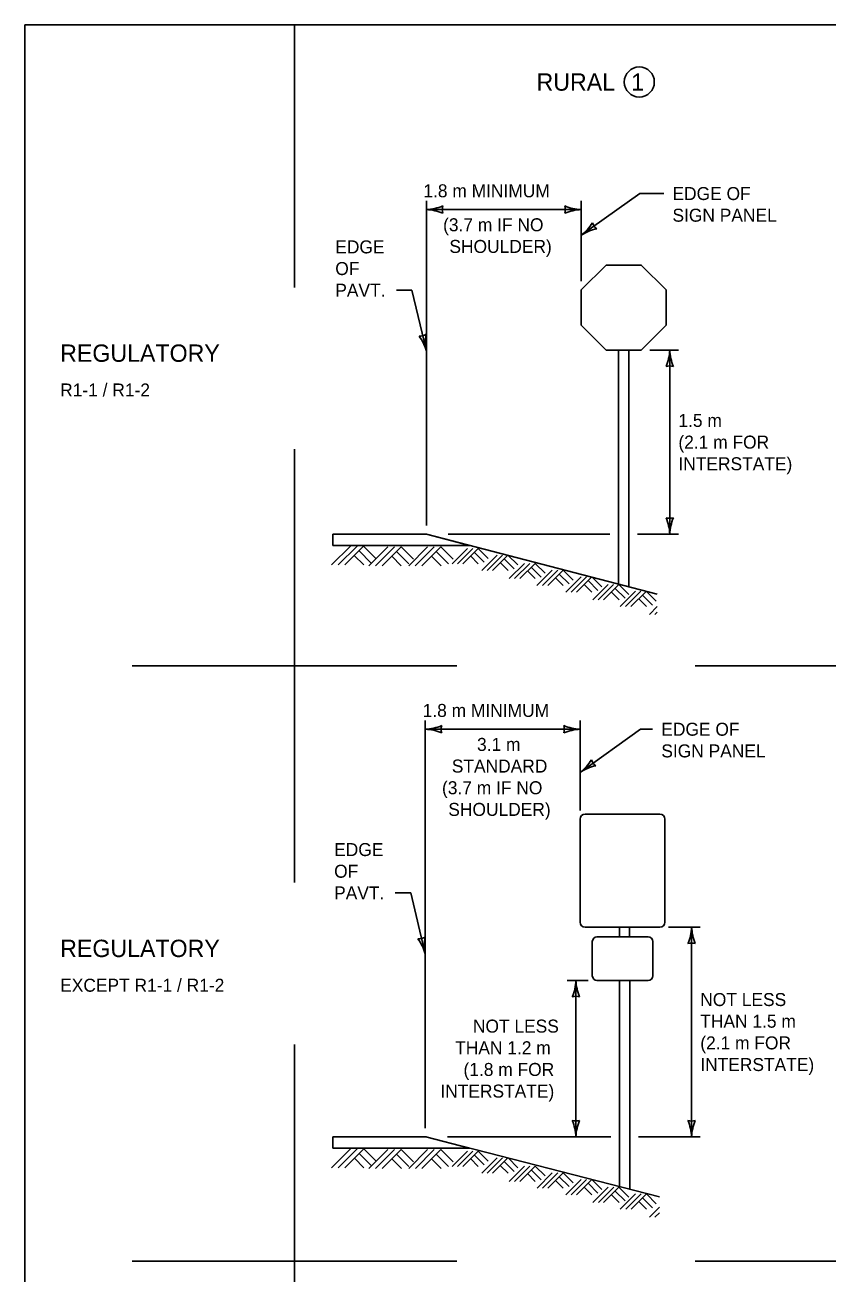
# Model space of a CAD drawing. Extents: x 49991.4 to 50021, y 49987.6 to 50011.4.
# Drawn here: x 49999.38 to 50003.09, y 49993.24 to 49999 of the extents above; entities that cross this region are included whole.
import ezdxf

# ---------------------------------------------------------------- set-up
doc = ezdxf.new("R2010")
doc.units = 0
for name, color, linetype in [('Level 1', 7, 'Continuous'), ('Level 2', 7, 'Continuous'), ('Level 3', 7, 'Continuous')]:
    doc.layers.add(name, color=color, linetype=linetype)

msp = doc.modelspace()

# ---------------------------------------------------------------- linework, layer by layer
at = {"layer": 'Level 1'}
for p, q in [((50002.124, 49996.4185), (50002.124, 49997.4987)), ((50002.1727, 49996.4059), (50002.1727, 49997.4987)), ((50001.2375, 49996.649), (50000.8056, 49996.649)), ((50000.8056, 49996.649), (50000.8056, 49996.5973)), ((50001.2374, 49996.649), (50000.8056, 49996.649)), ((50000.8056, 49996.649), (50000.8056, 49996.5973)), ((50001.2374, 49996.649), (50002.3037, 49996.3718)), ((50001.4363, 49996.5973), (50001.2374, 49996.649)), ((50000.7994, 49996.5068), (50000.8867, 49996.5941)), ((50000.8056, 49996.5973), (50001.4363, 49996.5973)), ((50000.8056, 49996.5973), (50001.4363, 49996.5973)), ((50000.83, 49996.5068), (50000.9173, 49996.5941)), ((50000.8605, 49996.5068), (50000.9477, 49996.5941)), ((50000.9263, 49996.5725), (50000.983, 49996.5158)), ((50000.9477, 49996.5941), (50001.0046, 49996.5373)), ((50000.9721, 49996.5031), (50001.0594, 49996.5905)), ((50001.0027, 49996.5031), (50001.0901, 49996.5905)), ((50001.0332, 49996.5031), (50001.1206, 49996.5905)), ((50001.099, 49996.5688), (50001.1558, 49996.5122)), ((50001.1206, 49996.5905), (50001.1774, 49996.5336)), ((50001.1556, 49996.5031), (50001.2429, 49996.5905)), ((50001.1863, 49996.5031), (50001.2736, 49996.5905)), ((50001.2167, 49996.5031), (50001.3041, 49996.5905)), ((50001.2825, 49996.5688), (50001.3393, 49996.5122)), ((50001.3041, 49996.5905), (50001.361, 49996.5336)), ((50001.3558, 49996.5125), (50001.4265, 49996.5833)), ((50001.3807, 49996.5125), (50001.4514, 49996.5833)), ((50001.4053, 49996.5125), (50001.4761, 49996.5833)), ((50001.4348, 49996.5977), (50001.4348, 49996.5973)), ((50001.4361, 49996.5973), (50001.4361, 49996.5973)), ((50001.4361, 49996.5973), (50001.4361, 49996.5973)), ((50001.4361, 49996.5973), (50001.4361, 49996.5973)), ((50001.4585, 49996.5659), (50001.5046, 49996.52)), ((50001.4761, 49996.5833), (50001.5222, 49996.5373)), ((50000.9046, 49996.5508), (50000.9488, 49996.5068)), ((50001.0774, 49996.5471), (50001.1215, 49996.5031)), ((50001.2608, 49996.5471), (50001.305, 49996.5031)), ((50001.4411, 49996.5483), (50001.4769, 49996.5125)), ((50001.4933, 49996.4819), (50001.564, 49996.5527)), ((50001.5181, 49996.4819), (50001.5889, 49996.5527)), ((50001.5428, 49996.4819), (50001.6135, 49996.5527)), ((50001.5785, 49996.5176), (50001.6145, 49996.4819)), ((50001.5961, 49996.5352), (50001.642, 49996.4892)), ((50001.6135, 49996.5527), (50001.6595, 49996.5067)), ((50001.6191, 49996.4437), (50001.6898, 49996.5143)), ((50001.6439, 49996.4437), (50001.7145, 49996.5143)), ((50001.6684, 49996.4437), (50001.7392, 49996.5143)), ((50001.7392, 49996.5143), (50001.7853, 49996.4683)), ((50001.7043, 49996.4794), (50001.7401, 49996.4437)), ((50001.7218, 49996.497), (50001.7678, 49996.451)), ((50001.748, 49996.4117), (50001.8187, 49996.4826)), ((50001.773, 49996.4117), (50001.8438, 49996.4826)), ((50001.7977, 49996.4117), (50001.8684, 49996.4826)), ((50001.8334, 49996.4474), (50001.8692, 49996.4117)), ((50001.8509, 49996.4651), (50001.8969, 49996.4192)), ((50001.8684, 49996.4826), (50001.9145, 49996.4365)), ((50001.8808, 49996.3813), (50001.9515, 49996.4521)), ((50001.9057, 49996.3813), (50001.9765, 49996.4521)), ((50001.9304, 49996.3813), (50001.9999, 49996.4508)), ((50002.0035, 49996.4499), (50002.0473, 49996.4063)), ((50001.9662, 49996.417), (50002.0018, 49996.3813)), ((50001.9837, 49996.4345), (50002.0296, 49996.3889)), ((50002.0063, 49996.3456), (50002.077, 49996.4164)), ((50002.0314, 49996.3456), (50002.1021, 49996.4164)), ((50002.0559, 49996.3456), (50002.1266, 49996.4164)), ((50002.1091, 49996.3989), (50002.1552, 49996.3529)), ((50002.1266, 49996.4164), (50002.1728, 49996.3703)), ((50002.1327, 49996.3145), (50002.2033, 49996.3853)), ((50002.1575, 49996.3145), (50002.2283, 49996.3853)), ((50002.1821, 49996.3145), (50002.2527, 49996.3851)), ((50002.2533, 49996.3849), (50002.299, 49996.3393)), ((50002.0916, 49996.3813), (50002.1274, 49996.3456)), ((50002.2179, 49996.3502), (50002.2537, 49996.3145)), ((50002.2354, 49996.3677), (50002.2814, 49996.3219)), ((50002.268, 49996.2787), (50002.3037, 49996.3144)), ((50002.2929, 49996.2787), (50002.3037, 49996.2895)), ((50001.97, 49995.3563), (50002.3161, 49995.3563)), ((50001.9475, 49994.8576), (50001.9475, 49995.3338)), ((50002.3386, 49995.3338), (50002.3386, 49994.8576)), ((50002.3161, 49994.8351), (50001.97, 49994.8351)), ((50002.1286, 49994.7902), (50002.1286, 49994.8351)), ((50002.1748, 49994.7902), (50002.1748, 49994.8351)), ((50002.0251, 49994.7902), (50002.2611, 49994.7902)), ((50002.0036, 49994.611), (50002.0036, 49994.7687)), ((50002.2826, 49994.7687), (50002.2826, 49994.611)), ((50002.2611, 49994.5895), (50002.0251, 49994.5895)), ((50002.1286, 49993.6382), (50002.1286, 49994.5895)), ((50002.1286, 49993.6382), (50002.1286, 49994.5895)), ((50002.1772, 49993.6257), (50002.1772, 49994.5895)), ((50002.1772, 49993.6257), (50002.1772, 49994.5895)), ((50001.2376, 49993.8673), (50000.8056, 49993.8673)), ((50000.8056, 49993.8673), (50000.8056, 49993.8156)), ((50001.2343, 49993.8673), (50000.8056, 49993.8673)), ((50000.8056, 49993.8673), (50000.8056, 49993.8156)), ((50001.2343, 49993.8673), (50002.3135, 49993.5908)), ((50001.4361, 49993.8156), (50001.2343, 49993.8673)), ((50000.7995, 49993.725), (50000.8868, 49993.8124)), ((50000.8056, 49993.8156), (50001.4362, 49993.8156)), ((50000.8056, 49993.8156), (50001.4361, 49993.8156)), ((50000.8301, 49993.725), (50000.9175, 49993.8124)), ((50000.8606, 49993.725), (50000.9479, 49993.8124)), ((50000.9479, 49993.8124), (50001.0048, 49993.7556)), ((50000.9723, 49993.7214), (50001.0596, 49993.8087)), ((50001.003, 49993.7214), (50001.0903, 49993.8087)), ((50001.0334, 49993.7214), (50001.1207, 49993.8087)), ((50001.1207, 49993.8087), (50001.1776, 49993.752)), ((50001.1558, 49993.7214), (50001.2431, 49993.8087)), ((50001.1865, 49993.7214), (50001.2738, 49993.8087)), ((50001.2169, 49993.7214), (50001.3042, 49993.8087)), ((50001.3042, 49993.8087), (50001.3611, 49993.752)), ((50001.356, 49993.7309), (50001.4267, 49993.8016)), ((50001.3809, 49993.7309), (50001.4516, 49993.8016)), ((50001.4055, 49993.7309), (50001.4762, 49993.8016)), ((50001.4362, 49993.8156), (50001.4362, 49993.8156)), ((50001.4762, 49993.8016), (50001.5223, 49993.7556)), ((50000.9047, 49993.7691), (50000.9489, 49993.725)), ((50000.9264, 49993.7908), (50000.9832, 49993.7341)), ((50001.0776, 49993.7654), (50001.1217, 49993.7214)), ((50001.0991, 49993.7871), (50001.1559, 49993.7305)), ((50001.2611, 49993.7654), (50001.3052, 49993.7214)), ((50001.2826, 49993.7871), (50001.3394, 49993.7305)), ((50001.4413, 49993.7666), (50001.4772, 49993.7309)), ((50001.4587, 49993.7842), (50001.5048, 49993.7383)), ((50001.4934, 49993.7002), (50001.5641, 49993.7709)), ((50001.5183, 49993.7002), (50001.589, 49993.7709)), ((50001.5429, 49993.7002), (50001.6131, 49993.7703)), ((50001.5787, 49993.7358), (50001.6146, 49993.7002)), ((50001.5963, 49993.7535), (50001.6422, 49993.7076)), ((50001.6148, 49993.7698), (50001.6597, 49993.7249)), ((50001.6192, 49993.6619), (50001.6899, 49993.7326)), ((50001.6441, 49993.6619), (50001.7148, 49993.7326)), ((50001.6687, 49993.6619), (50001.7394, 49993.7326)), ((50001.7045, 49993.6976), (50001.7402, 49993.6619)), ((50001.722, 49993.7152), (50001.768, 49993.6693)), ((50001.7394, 49993.7326), (50001.7855, 49993.6866)), ((50001.7482, 49993.6301), (50001.8189, 49993.7009)), ((50001.7732, 49993.6301), (50001.8439, 49993.7009)), ((50001.7978, 49993.6301), (50001.8685, 49993.7009)), ((50001.8511, 49993.6834), (50001.897, 49993.6375)), ((50001.8685, 49993.7009), (50001.9146, 49993.6548)), ((50001.8336, 49993.6657), (50001.8694, 49993.6301)), ((50001.881, 49993.5996), (50001.9517, 49993.6703)), ((50001.9059, 49993.5996), (50001.9767, 49993.6703)), ((50001.9306, 49993.5996), (50002.0013, 49993.6703)), ((50001.9664, 49993.6353), (50002.0021, 49993.5996)), ((50001.9839, 49993.6529), (50002.0298, 49993.6072)), ((50002.0013, 49993.6703), (50002.0474, 49993.6245)), ((50002.0066, 49993.5639), (50002.0773, 49993.6347)), ((50002.0315, 49993.5639), (50002.1023, 49993.6347)), ((50002.056, 49993.5639), (50002.1268, 49993.6347)), ((50002.1268, 49993.6347), (50002.173, 49993.5886)), ((50002.0918, 49993.5996), (50002.1276, 49993.5639)), ((50002.1093, 49993.6172), (50002.1554, 49993.5713)), ((50002.1328, 49993.5328), (50002.2035, 49993.6035)), ((50002.1577, 49993.5328), (50002.2285, 49993.6035)), ((50002.1823, 49993.5328), (50002.2531, 49993.6035)), ((50002.2182, 49993.5685), (50002.2539, 49993.5328)), ((50002.2357, 49993.5861), (50002.2816, 49993.5402)), ((50002.2531, 49993.6035), (50002.2992, 49993.5576)), ((50002.2682, 49993.4969), (50002.3135, 49993.5422)), ((50002.2931, 49993.4969), (50002.3135, 49993.5173))]:
    msp.add_line(p, q, dxfattribs=at)
for points in [[(49999.3835, 49998.9992), (50016.7501, 49998.9992), (50016.7501, 49987.7988), (49999.3835, 49987.7988)], [(50002.0669, 49997.8908), (50002.2297, 49997.8908), (50002.3444, 49997.7761), (50002.3444, 49997.6134), (50002.2297, 49997.4987), (50002.0669, 49997.4987), (50001.9523, 49997.6134), (50001.9523, 49997.7761)]]:
    msp.add_lwpolyline(points, close=True, dxfattribs=at)
for centre, radius, start, end in [((50001.97, 49995.3338), 0.0225, 90, 180), ((50002.3161, 49995.3338), 0.0225, 0, 90), ((50001.97, 49994.8576), 0.0225, 180, 270), ((50002.3161, 49994.8576), 0.0225, 270, 0), ((50002.0251, 49994.7687), 0.0215, 90, 180), ((50002.2611, 49994.7687), 0.0215, 0, 90), ((50002.0251, 49994.611), 0.0215, 180, 270), ((50002.2611, 49994.611), 0.0215, 270, 0)]:
    msp.add_arc(centre, radius, start, end, dxfattribs=at)
at = {"layer": 'Level 2'}
msp.add_circle((50002.2206, 49998.7359), 0.0693, dxfattribs=at)
at = {"layer": 'Level 3'}
for p, q in [((50000.6286, 49998.9992), (50000.6286, 49997.788)), ((50001.2375, 49996.689), (50001.2375, 49998.187)), ((50001.9523, 49998.0283), (50002.223, 49998.2211)), ((50001.9523, 49997.8161), (50001.9523, 49998.187)), ((50002.223, 49998.2211), (50002.3338, 49998.2211)), ((50001.2375, 49998.147), (50001.9523, 49998.147)), ((50001.0987, 49997.7749), (50001.1707, 49997.7749)), ((50001.1707, 49997.7749), (50001.2375, 49997.4934)), ((50002.2697, 49997.4987), (50002.4012, 49997.4987)), ((50002.3612, 49997.4987), (50002.3612, 49996.649)), ((50000.6286, 49995.0407), (50000.6286, 49997.0407)), ((50001.3374, 49996.649), (50002.084, 49996.649)), ((50002.2127, 49996.649), (50002.4012, 49996.649)), ((49999.8786, 49996.0407), (50001.3786, 49996.0407)), ((50002.4787, 49996.0407), (50003.9787, 49996.0407)), ((50001.2323, 49993.9073), (50001.2323, 49995.7886)), ((50001.9475, 49995.3738), (50001.9475, 49995.7886)), ((50001.9475, 49995.7486), (50001.2323, 49995.7486)), ((50001.9475, 49995.5496), (50002.2269, 49995.7486)), ((50002.2269, 49995.7486), (50002.2823, 49995.7486)), ((50001.0935, 49994.9932), (50001.1655, 49994.9932)), ((50001.1655, 49994.9932), (50001.2323, 49994.7117)), ((50002.3561, 49994.8351), (50002.5022, 49994.8351)), ((50002.4622, 49993.8669), (50002.4622, 49994.8351)), ((50001.888, 49994.5895), (50001.9851, 49994.5895)), ((50001.928, 49993.8673), (50001.928, 49994.5895)), ((50000.6286, 49992.2934), (50000.6286, 49994.2934)), ((50001.3343, 49993.8673), (50002.0886, 49993.8673)), ((50002.2172, 49993.8669), (50002.5022, 49993.8669)), ((49999.8786, 49993.2934), (50001.3786, 49993.2934)), ((50002.4787, 49993.2934), (50003.9787, 49993.2934))]:
    msp.add_line(p, q, dxfattribs=at)
for centre, radius, start, end in [((50001.226, 49998.3797), 0.233, 272.82731, 292.07716), ((50001.2283, 49997.9249), 0.2223, 67.45601, 87.63952), ((50001.3657, 49998.147), 0.0548, 162.13882, 197.86118), ((50001.9615, 49998.3691), 0.2223, 247.45601, 267.63952), ((50001.8241, 49998.147), 0.0548, 342.13882, 17.86118), ((50001.9638, 49997.9143), 0.233, 92.82731, 112.07716), ((50001.8079, 49998.2112), 0.233, 308.28683, 327.53668), ((50002.0737, 49997.8421), 0.2223, 102.91553, 123.09904), ((50002.0567, 49998.1027), 0.0548, 197.59834, 233.3207), ((50001.2079, 49997.6182), 0.0548, 265.4882, 301.21056), ((50001.0137, 49997.4285), 0.233, 16.17669, 35.42654), ((50001.4557, 49997.5358), 0.2223, 170.80539, 190.9889), ((50002.1391, 49997.5079), 0.2223, 337.45601, 357.63952), ((50002.5939, 49997.5102), 0.233, 182.82731, 202.07716), ((50002.3612, 49997.3705), 0.0548, 72.13882, 107.86118), ((50002.3612, 49996.7772), 0.0548, 252.13882, 287.86118), ((50002.1285, 49996.6375), 0.233, 2.82731, 22.07716), ((50002.5833, 49996.6398), 0.2223, 157.45601, 177.63952), ((50001.2208, 49995.9813), 0.233, 272.82731, 292.07716), ((50001.3605, 49995.7486), 0.0548, 162.13882, 197.86118), ((50001.9567, 49995.9707), 0.2223, 247.45601, 267.63952), ((50001.8193, 49995.7486), 0.0548, 342.13882, 17.86118), ((50001.2231, 49995.5265), 0.2223, 67.45601, 87.63952), ((50001.959, 49995.5159), 0.233, 92.82731, 112.07716), ((50001.8031, 49995.7325), 0.233, 308.28732, 327.53717), ((50002.0689, 49995.3634), 0.2223, 102.91602, 123.09953), ((50002.0519, 49995.624), 0.0548, 197.59883, 233.32119), ((50002.2401, 49994.8443), 0.2223, 337.45601, 357.63952), ((50002.6949, 49994.8466), 0.233, 182.82731, 202.07716), ((50001.2027, 49994.8365), 0.0548, 265.4882, 301.21056), ((50001.0085, 49994.6468), 0.233, 16.17669, 35.42654), ((50001.4505, 49994.7541), 0.2223, 170.80539, 190.9889), ((50002.4622, 49994.7069), 0.0548, 72.13882, 107.86118), ((50001.7059, 49994.5987), 0.2223, 337.45601, 357.63952), ((50002.1607, 49994.601), 0.233, 182.82731, 202.07716), ((50001.928, 49994.4613), 0.0548, 72.13882, 107.86118), ((50001.928, 49993.9955), 0.0548, 252.13882, 287.86118), ((50001.6953, 49993.8558), 0.233, 2.82731, 22.07716), ((50002.1501, 49993.8581), 0.2223, 157.45601, 177.63952), ((50002.4622, 49993.9951), 0.0548, 252.13882, 287.86118), ((50002.2295, 49993.8554), 0.233, 2.82731, 22.07716), ((50002.6843, 49993.8577), 0.2223, 157.45601, 177.63952)]:
    msp.add_arc(centre, radius, start, end, dxfattribs=at)

# ---------------------------------------------------------------- texts
at = {"layer": 'Level 2'}
for s, height, p in [('RURAL', 0.08, (50001.746, 49998.6959)), ('1', 0.08, (50002.1832, 49998.6958)), ('1.8 m MINIMUM', 0.06, (50001.2234, 49998.2038)), ('EDGE OF', 0.06, (50002.3738, 49998.1911)), ('SIGN PANEL', 0.06, (50002.3738, 49998.0911)), ('(3.7 m IF NO', 0.06, (50001.3145, 49998.047)), ('EDGE', 0.06, (50000.8166, 49997.9449)), ('SHOULDER)', 0.06, (50001.3437, 49997.947)), ('OF', 0.06, (50000.8166, 49997.8449)), ('PAVT.', 0.06, (50000.8166, 49997.7449)), ('REGULATORY', 0.08, (49999.5462, 49997.4444)), ('R1-1 / R1-2', 0.06, (49999.5462, 49997.2844)), ('1.5 m', 0.06, (50002.4012, 49997.1438)), ('(2.1 m FOR', 0.06, (50002.4012, 49997.0438)), ('INTERSTATE)', 0.06, (50002.4012, 49996.9438)), ('1.8 m MINIMUM', 0.06, (50001.2202, 49995.8054)), ('EDGE OF', 0.06, (50002.3223, 49995.7186)), ('3.1 m', 0.06, (50001.4712, 49995.6486)), ('SIGN PANEL', 0.06, (50002.3223, 49995.6186)), ('STANDARD', 0.06, (50001.3547, 49995.5486)), ('(3.7 m IF NO', 0.06, (50001.3095, 49995.4486)), ('SHOULDER)', 0.06, (50001.3387, 49995.3486)), ('EDGE', 0.06, (50000.8114, 49995.1632)), ('OF', 0.06, (50000.8114, 49995.0632)), ('PAVT.', 0.06, (50000.8114, 49994.9632)), ('REGULATORY', 0.08, (49999.5462, 49994.6971)), ('EXCEPT R1-1 / R1-2', 0.06, (49999.5462, 49994.5371)), ('NOT LESS', 0.06, (50002.5022, 49994.471)), ('THAN 1.5 m', 0.06, (50002.5022, 49994.371)), ('NOT LESS', 0.06, (50001.4523, 49994.3484)), ('(2.1 m FOR', 0.06, (50002.5022, 49994.271)), ('THAN 1.2 m', 0.06, (50001.3703, 49994.2484)), ('(1.8 m FOR', 0.06, (50001.4087, 49994.1484)), ('INTERSTATE)', 0.06, (50002.5022, 49994.171)), ('INTERSTATE)', 0.06, (50001.3019, 49994.0484))]:
    msp.add_text(s, height=height, dxfattribs=at).set_placement(p)

doc.saveas('drawing.dxf')
